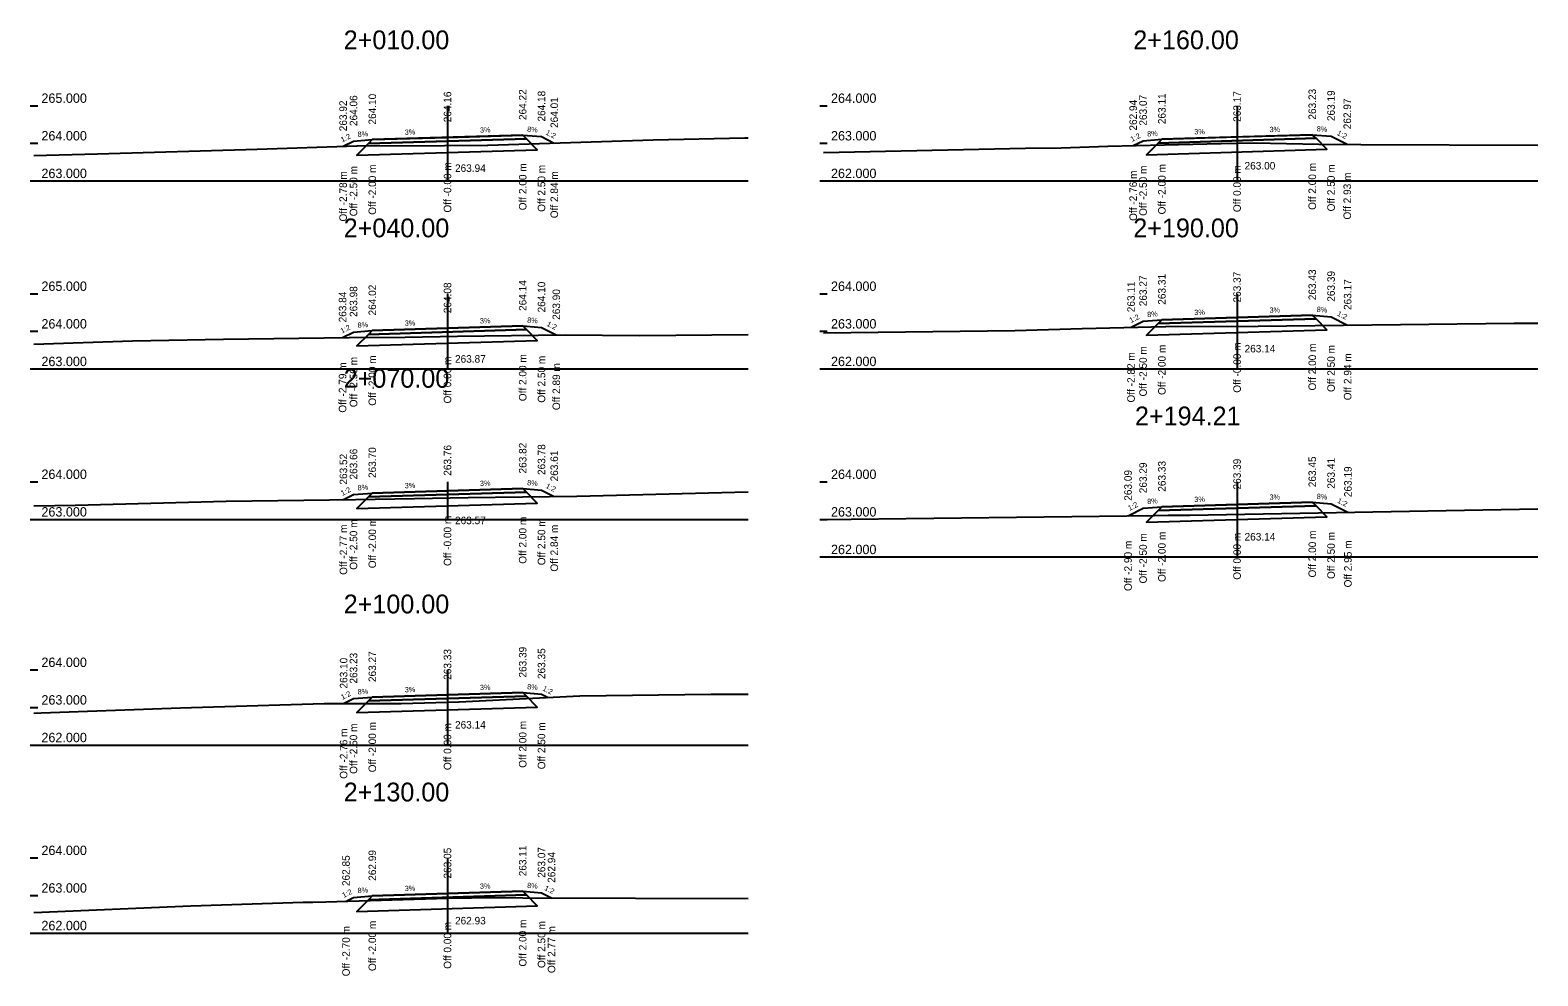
# Model space of a CAD drawing. Extents: x -550605 to -538780, y -1102367 to -1093705.
# Drawn here: x -541079.9 to -541039.8, y -1098198.69 to -1098173.55 of the extents above; entities that cross this region are included whole.
import ezdxf

# ---------------------------------------------------------------- set-up
doc = ezdxf.new("R2010")
doc.units = 0
for name, color, linetype in [('PŘ - offsety od osy', 7, 'Continuous'), ('PŘ - popis', 7, 'Continuous'), ('PŘ - příčné sklony', 7, 'Continuous'), ('PŘ - terén', 7, 'Continuous'), ('PŘ - vozovka', 7, 'Continuous'), ('PŘ - výšky offsetů', 7, 'Continuous')]:
    doc.layers.add(name, color=color, linetype=linetype)

msp = doc.modelspace()

# ---------------------------------------------------------------- linework, layer by layer
at = {"layer": 'PŘ - popis'}
for p, q in [((-541079.898, -1098175.553), (-541079.698, -1098175.553)), ((-541068.798, -1098175.553), (-541068.798, -1098177.553)), ((-541058.898, -1098175.553), (-541058.698, -1098175.553)), ((-541047.798, -1098175.553), (-541047.798, -1098177.553)), ((-541079.898, -1098176.553), (-541079.698, -1098176.553)), ((-541058.898, -1098176.553), (-541058.698, -1098176.553)), ((-541079.898, -1098177.553), (-541079.698, -1098177.553)), ((-541079.798, -1098177.553), (-541060.798, -1098177.553)), ((-541058.898, -1098177.553), (-541058.698, -1098177.553)), ((-541058.798, -1098177.553), (-541039.798, -1098177.553)), ((-541079.898, -1098180.553), (-541079.698, -1098180.553)), ((-541068.798, -1098180.553), (-541068.798, -1098182.553)), ((-541058.898, -1098180.553), (-541058.698, -1098180.553)), ((-541047.798, -1098180.553), (-541047.798, -1098182.553)), ((-541079.898, -1098181.553), (-541079.698, -1098181.553)), ((-541058.898, -1098181.553), (-541058.698, -1098181.553)), ((-541079.898, -1098182.553), (-541079.698, -1098182.553)), ((-541079.798, -1098182.553), (-541060.798, -1098182.553)), ((-541058.898, -1098182.553), (-541058.698, -1098182.553)), ((-541058.798, -1098182.553), (-541039.798, -1098182.553)), ((-541079.898, -1098185.553), (-541079.698, -1098185.553)), ((-541068.798, -1098185.553), (-541068.798, -1098186.553)), ((-541058.898, -1098185.553), (-541058.698, -1098185.553)), ((-541047.798, -1098185.553), (-541047.798, -1098187.553)), ((-541079.898, -1098186.553), (-541079.698, -1098186.553)), ((-541079.798, -1098186.553), (-541060.798, -1098186.553)), ((-541058.898, -1098186.553), (-541058.698, -1098186.553)), ((-541058.898, -1098187.553), (-541058.698, -1098187.553)), ((-541058.798, -1098187.553), (-541039.798, -1098187.553)), ((-541079.898, -1098190.553), (-541079.698, -1098190.553)), ((-541068.798, -1098190.553), (-541068.798, -1098192.553)), ((-541079.898, -1098191.553), (-541079.698, -1098191.553)), ((-541079.898, -1098192.553), (-541079.698, -1098192.553)), ((-541079.798, -1098192.553), (-541060.798, -1098192.553)), ((-541079.898, -1098195.553), (-541079.698, -1098195.553)), ((-541068.798, -1098195.553), (-541068.798, -1098197.553)), ((-541079.898, -1098196.553), (-541079.698, -1098196.553)), ((-541079.898, -1098197.553), (-541079.698, -1098197.553)), ((-541079.798, -1098197.553), (-541060.798, -1098197.553))]:
    msp.add_line(p, q, dxfattribs=at)
at = {"layer": 'PŘ - terén'}
for points in [[(-541079.798, -1098176.875), (-541078.108, -1098176.835), (-541073.856, -1098176.707), (-541071.206, -1098176.621), (-541071.204, -1098176.621), (-541068.882, -1098176.615), (-541067.728, -1098176.601), (-541067.728, -1098176.601), (-541063.324, -1098176.463), (-541060.887, -1098176.406), (-541060.798, -1098176.406)], [(-541058.798, -1098176.795), (-541053.427, -1098176.685), (-541052.479, -1098176.674), (-541051.233, -1098176.632), (-541048.217, -1098176.56), (-541047.348, -1098176.538), (-541047.347, -1098176.538), (-541045.626, -1098176.576), (-541044.502, -1098176.582), (-541039.798, -1098176.606)], [(-541058.798, -1098181.589), (-541053.705, -1098181.531), (-541051.916, -1098181.481), (-541049.697, -1098181.421), (-541049.696, -1098181.421), (-541047.241, -1098181.412), (-541040.424, -1098181.339), (-541039.798, -1098181.337)], [(-541079.798, -1098181.892), (-541077.174, -1098181.807), (-541074.754, -1098181.763), (-541071.416, -1098181.714), (-541069.928, -1098181.707), (-541068.529, -1098181.68), (-541065.665, -1098181.645), (-541063.691, -1098181.663), (-541060.798, -1098181.636)], [(-541079.798, -1098186.194), (-541078.695, -1098186.174), (-541074.684, -1098186.073), (-541071.242, -1098186.023), (-541071.241, -1098186.023), (-541069.676, -1098185.998), (-541068.247, -1098185.971), (-541068.245, -1098185.971), (-541065.36, -1098185.936), (-541060.798, -1098185.819)], [(-541058.798, -1098186.556), (-541049.99, -1098186.449), (-541049.632, -1098186.445), (-541049.582, -1098186.444), (-541049.521, -1098186.442), (-541049.521, -1098186.442), (-541049.453, -1098186.442), (-541049.051, -1098186.437), (-541039.798, -1098186.271)], [(-541079.798, -1098191.706), (-541079.609, -1098191.699), (-541075.897, -1098191.567), (-541072.078, -1098191.452), (-541070.029, -1098191.446), (-541068.488, -1098191.407), (-541068.488, -1098191.407), (-541065.28, -1098191.243), (-541061.781, -1098191.204), (-541060.798, -1098191.203)], [(-541079.798, -1098197.01), (-541075.622, -1098196.825), (-541072.638, -1098196.728), (-541072.377, -1098196.727), (-541072.377, -1098196.727), (-541072.038, -1098196.719), (-541068.799, -1098196.623), (-541068.799, -1098196.623), (-541067.511, -1098196.611), (-541066.794, -1098196.614), (-541060.798, -1098196.636)]]:
    msp.add_lwpolyline(points, dxfattribs=at)
at = {"layer": 'PŘ - vozovka'}
for points in [[(-541071.574, -1098176.633), (-541071.298, -1098176.495), (-541070.798, -1098176.455), (-541068.798, -1098176.395), (-541066.798, -1098176.335), (-541066.298, -1098176.375), (-541065.958, -1098176.546)], [(-541050.561, -1098176.616), (-541050.298, -1098176.484), (-541049.798, -1098176.444), (-541047.798, -1098176.384), (-541045.798, -1098176.324), (-541045.298, -1098176.364), (-541044.867, -1098176.58)], [(-541050.618, -1098181.446), (-541050.298, -1098181.286), (-541049.798, -1098181.246), (-541047.798, -1098181.186), (-541045.798, -1098181.126), (-541045.298, -1098181.166), (-541044.857, -1098181.386)], [(-541071.589, -1098181.716), (-541071.298, -1098181.571), (-541070.798, -1098181.531), (-541068.798, -1098181.471), (-541066.798, -1098181.411), (-541066.298, -1098181.451), (-541065.904, -1098181.648)], [(-541071.567, -1098186.028), (-541071.298, -1098185.893), (-541070.798, -1098185.853), (-541068.798, -1098185.793), (-541066.798, -1098185.733), (-541066.298, -1098185.773), (-541065.959, -1098185.943)], [(-541050.698, -1098186.458), (-541050.298, -1098186.258), (-541049.798, -1098186.218), (-541047.798, -1098186.158), (-541045.798, -1098186.098), (-541045.298, -1098186.138), (-541044.85, -1098186.362)], [(-541071.561, -1098191.451), (-541071.298, -1098191.319), (-541070.798, -1098191.279), (-541068.798, -1098191.219), (-541066.798, -1098191.159), (-541066.298, -1098191.199), (-541066.124, -1098191.286)], [(-541071.497, -1098196.703), (-541071.298, -1098196.603), (-541070.798, -1098196.563), (-541068.798, -1098196.503), (-541066.798, -1098196.443), (-541066.298, -1098196.483), (-541066.031, -1098196.617)]]:
    msp.add_lwpolyline(points, dxfattribs=at)
for points in [[(-541070.898, -1098176.558), (-541071.211, -1098176.868), (-541066.409, -1098176.724), (-541066.698, -1098176.432)], [(-541070.798, -1098176.455), (-541070.898, -1098176.558), (-541066.698, -1098176.432), (-541066.798, -1098176.335)], [(-541049.898, -1098176.547), (-541050.211, -1098176.857), (-541045.409, -1098176.713), (-541045.698, -1098176.421)], [(-541049.798, -1098176.444), (-541049.898, -1098176.547), (-541045.698, -1098176.421), (-541045.798, -1098176.324)], [(-541049.898, -1098181.349), (-541050.211, -1098181.658), (-541045.409, -1098181.514), (-541045.698, -1098181.223)], [(-541049.798, -1098181.246), (-541049.898, -1098181.349), (-541045.698, -1098181.223), (-541045.798, -1098181.126)], [(-541070.898, -1098181.634), (-541071.211, -1098181.943), (-541066.409, -1098181.799), (-541066.698, -1098181.508)], [(-541070.798, -1098181.531), (-541070.898, -1098181.634), (-541066.698, -1098181.508), (-541066.798, -1098181.411)], [(-541070.798, -1098185.853), (-541070.898, -1098185.956), (-541066.698, -1098185.83), (-541066.798, -1098185.733)], [(-541070.898, -1098185.956), (-541071.211, -1098186.266), (-541066.409, -1098186.122), (-541066.698, -1098185.83)], [(-541049.898, -1098186.321), (-541050.211, -1098186.63), (-541045.409, -1098186.486), (-541045.698, -1098186.195)], [(-541049.798, -1098186.218), (-541049.898, -1098186.321), (-541045.698, -1098186.195), (-541045.798, -1098186.098)], [(-541070.898, -1098191.382), (-541071.211, -1098191.692), (-541066.409, -1098191.548), (-541066.698, -1098191.256)], [(-541070.798, -1098191.279), (-541070.898, -1098191.382), (-541066.698, -1098191.256), (-541066.798, -1098191.159)], [(-541070.898, -1098196.666), (-541071.211, -1098196.976), (-541066.409, -1098196.832), (-541066.698, -1098196.54)], [(-541070.798, -1098196.563), (-541070.898, -1098196.666), (-541066.698, -1098196.54), (-541066.798, -1098196.443)]]:
    msp.add_lwpolyline(points, close=True, dxfattribs=at)

# ---------------------------------------------------------------- texts
at = {"layer": 'PŘ - offsety od osy'}
for s, p in [('Off -2.78 m', (-541071.474, -1098178.633)), ('Off -2.50 m', (-541071.198, -1098178.495)), ('Off -2.00 m', (-541070.698, -1098178.455)), ('Off -0.00 m', (-541068.698, -1098178.395)), ('Off 2.00 m', (-541066.698, -1098178.335)), ('Off 2.50 m', (-541066.198, -1098178.375)), ('Off 2.84 m', (-541065.858, -1098178.546)), ('Off -2.76 m', (-541050.461, -1098178.616)), ('Off -2.50 m', (-541050.198, -1098178.484)), ('Off -2.00 m', (-541049.698, -1098178.444)), ('Off 0.00 m', (-541047.698, -1098178.384)), ('Off 2.00 m', (-541045.698, -1098178.324)), ('Off 2.50 m', (-541045.198, -1098178.364)), ('Off 2.93 m', (-541044.767, -1098178.58)), ('Off 2.00 m', (-541066.698, -1098183.411)), ('Off -2.82 m', (-541050.518, -1098183.446)), ('Off -2.50 m', (-541050.198, -1098183.286)), ('Off -2.00 m', (-541049.698, -1098183.246)), ('Off -0.00 m', (-541047.698, -1098183.186)), ('Off 2.00 m', (-541045.698, -1098183.126)), ('Off 2.50 m', (-541045.198, -1098183.166)), ('Off 2.94 m', (-541044.757, -1098183.386)), ('Off -2.79 m', (-541071.489, -1098183.716)), ('Off -2.50 m', (-541071.198, -1098183.571)), ('Off -2.00 m', (-541070.698, -1098183.531)), ('Off 0.00 m', (-541068.698, -1098183.471)), ('Off 2.50 m', (-541066.198, -1098183.451)), ('Off 2.89 m', (-541065.804, -1098183.648)), ('Off -2.50 m', (-541071.198, -1098187.893)), ('Off -2.00 m', (-541070.698, -1098187.853)), ('Off -0.00 m', (-541068.698, -1098187.793)), ('Off 2.00 m', (-541066.698, -1098187.733)), ('Off 2.50 m', (-541066.198, -1098187.773)), ('Off -2.77 m', (-541071.467, -1098188.028)), ('Off 2.84 m', (-541065.859, -1098187.943)), ('Off -2.50 m', (-541050.198, -1098188.258)), ('Off -2.00 m', (-541049.698, -1098188.218)), ('Off 0.00 m', (-541047.698, -1098188.158)), ('Off 2.00 m', (-541045.698, -1098188.098)), ('Off 2.50 m', (-541045.198, -1098188.138)), ('Off -2.90 m', (-541050.598, -1098188.458)), ('Off 2.95 m', (-541044.75, -1098188.362)), ('Off -2.76 m', (-541071.461, -1098193.451)), ('Off -2.50 m', (-541071.198, -1098193.319)), ('Off -2.00 m', (-541070.698, -1098193.279)), ('Off 0.00 m', (-541068.698, -1098193.219)), ('Off 2.00 m', (-541066.698, -1098193.159)), ('Off 2.50 m', (-541066.198, -1098193.199)), ('Off -2.70 m', (-541071.397, -1098198.703)), ('Off -2.00 m', (-541070.698, -1098198.563)), ('Off 0.00 m', (-541068.698, -1098198.503)), ('Off 2.00 m', (-541066.698, -1098198.443)), ('Off 2.50 m', (-541066.198, -1098198.483)), ('Off 2.77 m', (-541065.931, -1098198.617))]:
    msp.add_text(s, height=0.2, rotation=90, dxfattribs=at).set_placement(p)
at = {"layer": 'PŘ - popis'}
for s, height, p in [('2+010.00', 0.5, (-541071.558, -1098174.053)), ('2+160.00', 0.5, (-541050.558, -1098174.053)), ('265.000', 0.25, (-541079.598, -1098175.478)), ('264.000', 0.25, (-541058.598, -1098175.478)), ('264.000', 0.25, (-541079.598, -1098176.478)), ('263.000', 0.25, (-541058.598, -1098176.478)), ('263.000', 0.25, (-541079.598, -1098177.478)), ('262.000', 0.25, (-541058.598, -1098177.478)), ('2+040.00', 0.5, (-541071.558, -1098179.053)), ('2+190.00', 0.5, (-541050.558, -1098179.053)), ('265.000', 0.25, (-541079.598, -1098180.478)), ('264.000', 0.25, (-541058.598, -1098180.478)), ('264.000', 0.25, (-541079.598, -1098181.478)), ('263.000', 0.25, (-541058.598, -1098181.478)), ('263.000', 0.25, (-541079.598, -1098182.478)), ('2+070.00', 0.5, (-541071.558, -1098183.053)), ('262.000', 0.25, (-541058.598, -1098182.478)), ('2+194.21', 0.5, (-541050.513, -1098184.053)), ('264.000', 0.25, (-541079.598, -1098185.478)), ('264.000', 0.25, (-541058.598, -1098185.478)), ('263.000', 0.25, (-541079.598, -1098186.478)), ('263.000', 0.25, (-541058.598, -1098186.478)), ('262.000', 0.25, (-541058.598, -1098187.478)), ('2+100.00', 0.5, (-541071.558, -1098189.053)), ('264.000', 0.25, (-541079.598, -1098190.478)), ('263.000', 0.25, (-541079.598, -1098191.478)), ('262.000', 0.25, (-541079.598, -1098192.478)), ('2+130.00', 0.5, (-541071.558, -1098194.053)), ('264.000', 0.25, (-541079.598, -1098195.478)), ('263.000', 0.25, (-541079.598, -1098196.478)), ('262.000', 0.25, (-541079.598, -1098197.478))]:
    msp.add_text(s, height=height, dxfattribs=at).set_placement(p)
at = {"layer": 'PŘ - příčné sklony'}
for s, rotation, p in [('3%', 1.7184, (-541069.933, -1098176.33)), ('3%', 1.7184, (-541067.933, -1098176.27)), ('8%', 355.4261, (-541066.683, -1098176.245)), ('3%', 1.7184, (-541048.933, -1098176.318)), ('3%', 1.7184, (-541046.933, -1098176.258)), ('8%', 355.4261, (-541045.683, -1098176.233)), ('1:2', 26.5651, (-541071.597, -1098176.533)), ('8%', 4.5739, (-541071.183, -1098176.386)), ('1:2', 333.4349, (-541066.2, -1098176.313)), ('1:2', 26.5651, (-541050.591, -1098176.519)), ('8%', 4.5739, (-541050.183, -1098176.375)), ('1:2', 333.4349, (-541045.155, -1098176.324)), ('3%', 1.7184, (-541048.933, -1098181.12)), ('3%', 1.7184, (-541046.933, -1098181.06)), ('8%', 355.4261, (-541045.683, -1098181.035)), ('1:2', 26.5651, (-541071.605, -1098181.613)), ('8%', 4.5739, (-541071.183, -1098181.462)), ('3%', 1.7184, (-541069.933, -1098181.405)), ('3%', 1.7184, (-541067.933, -1098181.345)), ('8%', 355.4261, (-541066.683, -1098181.32)), ('1:2', 333.4349, (-541066.173, -1098181.402)), ('1:2', 26.5651, (-541050.62, -1098181.335)), ('8%', 4.5739, (-541050.183, -1098181.176)), ('1:2', 333.4349, (-541045.15, -1098181.128)), ('1:2', 26.5651, (-541071.594, -1098185.93)), ('8%', 4.5739, (-541071.183, -1098185.784)), ('3%', 1.7184, (-541069.933, -1098185.727)), ('3%', 1.7184, (-541067.933, -1098185.667)), ('8%', 355.4261, (-541066.683, -1098185.643)), ('1:2', 333.4349, (-541066.2, -1098185.71)), ('1:2', 26.5651, (-541050.659, -1098186.327)), ('8%', 4.5739, (-541050.183, -1098186.149)), ('3%', 1.7184, (-541048.933, -1098186.092)), ('3%', 1.7184, (-541046.933, -1098186.032)), ('8%', 355.4261, (-541045.683, -1098186.007)), ('1:2', 333.4349, (-541045.146, -1098186.102)), ('3%', 1.7184, (-541069.933, -1098191.153)), ('3%', 1.7184, (-541067.933, -1098191.093)), ('8%', 355.4261, (-541066.683, -1098191.068)), ('1:2', 333.4349, (-541066.283, -1098191.095)), ('1:2', 26.5651, (-541071.591, -1098191.354)), ('8%', 4.5739, (-541071.183, -1098191.21)), ('3%', 1.7184, (-541067.933, -1098196.377)), ('8%', 355.4261, (-541066.683, -1098196.353)), ('1:2', 26.5651, (-541071.559, -1098196.622)), ('8%', 4.5739, (-541071.183, -1098196.494)), ('3%', 1.7184, (-541069.933, -1098196.437)), ('1:2', 333.4349, (-541066.237, -1098196.402))]:
    msp.add_text(s, height=0.14, rotation=rotation, dxfattribs=at).set_placement(p)
at = {"layer": 'PŘ - výšky offsetů'}
for s, p in [('264.06', (-541071.198, -1098176.095)), ('264.10', (-541070.698, -1098176.055)), ('264.16', (-541068.698, -1098175.995)), ('264.22', (-541066.698, -1098175.935)), ('264.18', (-541066.198, -1098175.975)), ('264.01', (-541065.858, -1098176.146)), ('263.07', (-541050.198, -1098176.084)), ('263.11', (-541049.698, -1098176.044)), ('263.17', (-541047.698, -1098175.984)), ('263.23', (-541045.698, -1098175.924)), ('263.19', (-541045.198, -1098175.964)), ('262.97', (-541044.767, -1098176.18)), ('263.92', (-541071.474, -1098176.233)), ('262.94', (-541050.461, -1098176.216)), ('264.14', (-541066.698, -1098181.011)), ('263.27', (-541050.198, -1098180.886)), ('263.31', (-541049.698, -1098180.846)), ('263.37', (-541047.698, -1098180.786)), ('263.43', (-541045.698, -1098180.726)), ('263.39', (-541045.198, -1098180.766)), ('263.17', (-541044.757, -1098180.986)), ('263.84', (-541071.489, -1098181.316)), ('263.98', (-541071.198, -1098181.171)), ('264.02', (-541070.698, -1098181.131)), ('264.08', (-541068.698, -1098181.071)), ('264.10', (-541066.198, -1098181.051)), ('263.90', (-541065.804, -1098181.248)), ('263.11', (-541050.518, -1098181.046)), ('263.76', (-541068.698, -1098185.393)), ('263.82', (-541066.698, -1098185.333)), ('263.78', (-541066.198, -1098185.373)), ('263.52', (-541071.467, -1098185.628)), ('263.66', (-541071.198, -1098185.493)), ('263.70', (-541070.698, -1098185.453)), ('263.61', (-541065.859, -1098185.543)), ('263.33', (-541049.698, -1098185.818)), ('263.39', (-541047.698, -1098185.758)), ('263.45', (-541045.698, -1098185.698)), ('263.41', (-541045.198, -1098185.738)), ('263.09', (-541050.598, -1098186.058)), ('263.29', (-541050.198, -1098185.858)), ('263.19', (-541044.75, -1098185.962)), ('263.23', (-541071.198, -1098190.919)), ('263.27', (-541070.698, -1098190.879)), ('263.33', (-541068.698, -1098190.819)), ('263.39', (-541066.698, -1098190.759)), ('263.35', (-541066.198, -1098190.799)), ('263.10', (-541071.461, -1098191.051)), ('262.99', (-541070.698, -1098196.163)), ('263.05', (-541068.698, -1098196.103)), ('263.11', (-541066.698, -1098196.043)), ('263.07', (-541066.198, -1098196.083)), ('262.94', (-541065.931, -1098196.217)), ('262.85', (-541071.397, -1098196.303))]:
    msp.add_text(s, height=0.2, rotation=90, dxfattribs=at).set_placement(p)
for s, p in [('263.94', (-541068.598, -1098177.314)), ('263.00', (-541047.598, -1098177.25)), ('263.87', (-541068.598, -1098182.386)), ('263.14', (-541047.598, -1098182.114)), ('263.57', (-541068.598, -1098186.681)), ('263.14', (-541047.598, -1098187.115)), ('263.14', (-541068.598, -1098192.115)), ('262.93', (-541068.598, -1098197.323))]:
    msp.add_text(s, height=0.2, dxfattribs=at).set_placement(p)

doc.saveas('drawing.dxf')
